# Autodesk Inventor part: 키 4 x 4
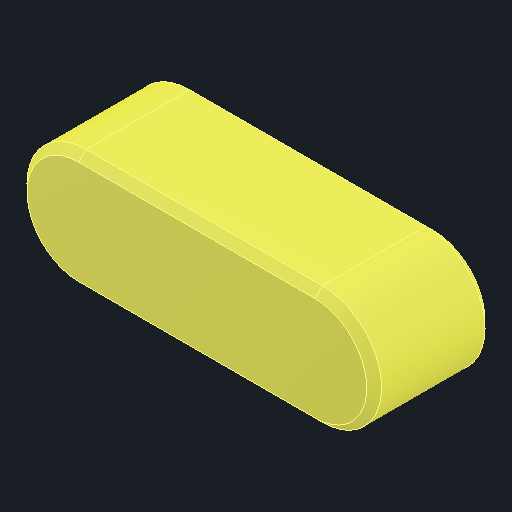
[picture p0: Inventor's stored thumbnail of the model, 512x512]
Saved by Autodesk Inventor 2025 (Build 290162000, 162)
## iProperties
Created: 2025-08
Part Number: 키 4 x 4
Material: 강철, 연강
Description: 키 및 해당 키홈
Document SubType Name: Modeling
Designer: infra08
Density: 7.86 g/cm^3
Appearance: 기본값
Author: jhkim
Sending System: Autodesk Inventor 2026
Preprocessor: ST-DEVELOPER v20.1
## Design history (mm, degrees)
feature "Solid1"
node "솔리드1"
